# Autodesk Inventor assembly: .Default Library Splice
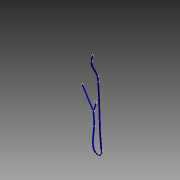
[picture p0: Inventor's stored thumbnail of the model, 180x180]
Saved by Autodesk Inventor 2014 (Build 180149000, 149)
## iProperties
Part Number: .Default Library Splice
Material: Default
Description: Default Library Splice
ParentFileIdentifier: 5|1|0|0|108|1|0|0|80|0|65|0|84|0|72|0|83|0|59|0|67|0|58|0|92|0|86|0|97|0|117|0|108|0|116|0|32|0|87|0|111|0|114|0|107|0|115|0|112|0|97|0|99|0|101|0|92|0|69|0|110
Created: 2009-02
Part Number: 100500.Harness1
Document SubType Name: Assembly
Designer: Autodesk
HarnessSettings: <HarnessSettings><Defaults><Segments><Diameter value="0.200 in" fromwires="True"/><Offset value="0.100 in"/><ColorStyle value="Blue"/><RoundUp value=""/><BendRa
Author: Autodesk
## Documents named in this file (2)
- C:\Users\iTools\Desktop\tutorial files\Automotive\100500\100500.Harness1.iam
- C:\Users\iTools\Desktop\tutorial files\Automotive\100500\100500.Harness1.ipt
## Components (2 placed, 2 different names)
1. Harness1
2. HA_VC_141:1
